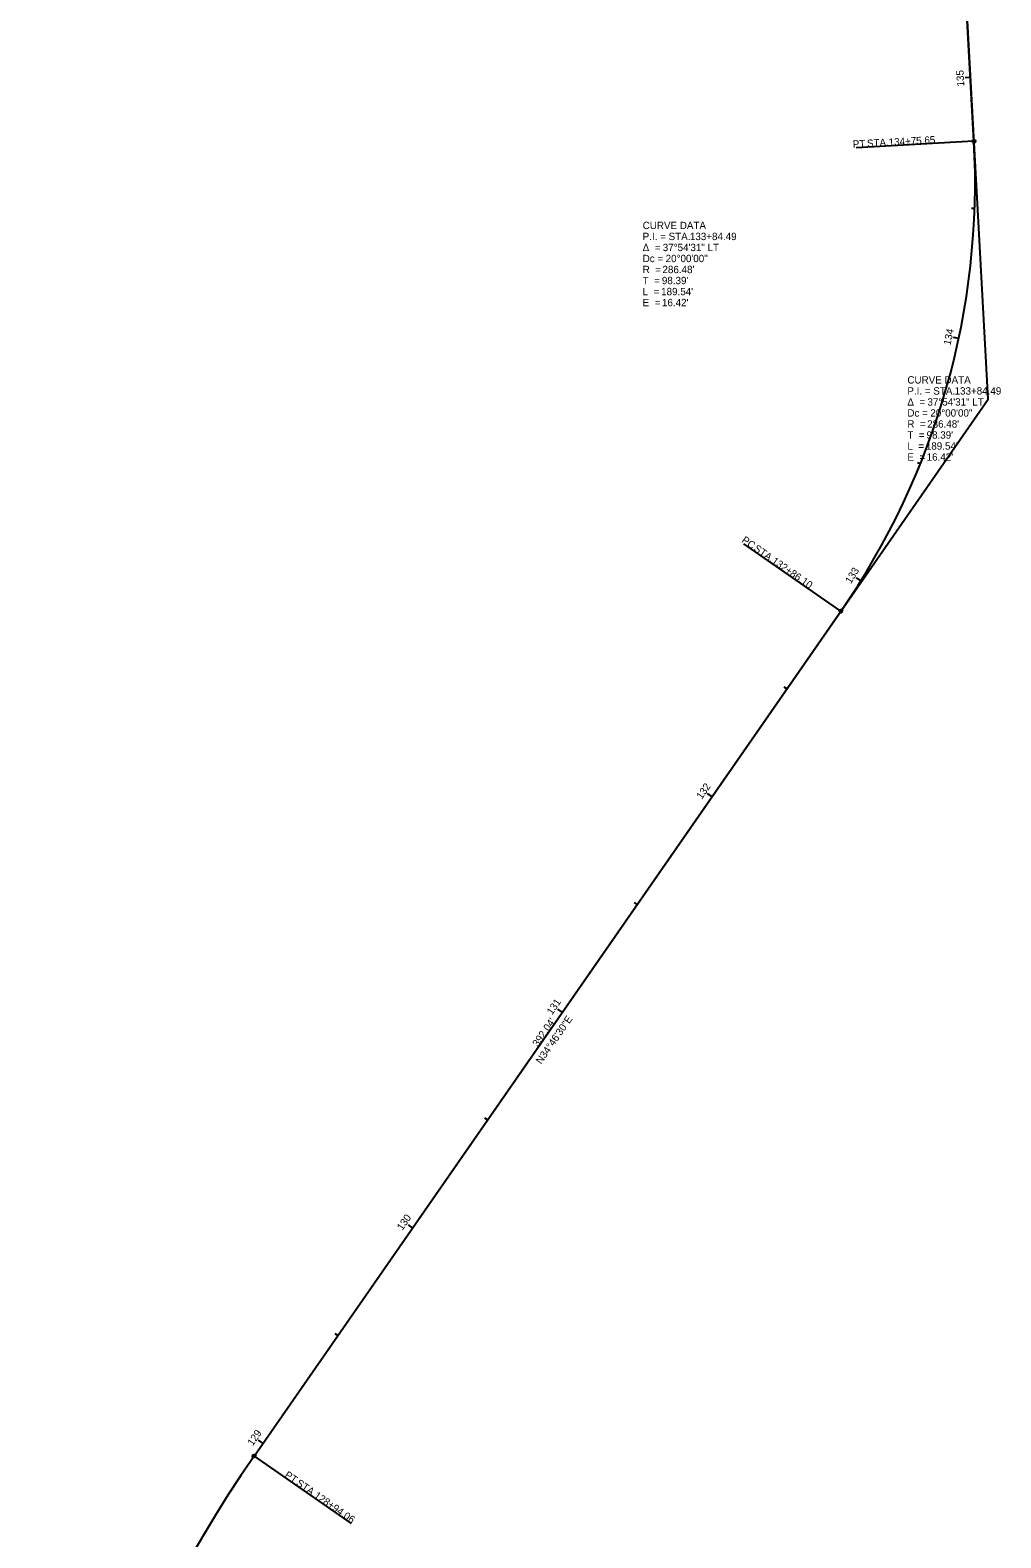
# Model space of a CAD drawing. Extents: x 177110 to 177558, y 286252 to 294117.
# Drawn here: x 177177 to 177547, y 288718 to 289293 of the extents above; entities that cross this region are included whole.
import ezdxf

# ---------------------------------------------------------------- set-up
doc = ezdxf.new("R2010")
doc.units = 0
for name, color, linetype in [('GE_X_Alignment_500_Bearings', 7, 'Continuous'), ('GE_X_Alignment_500_Cardinal_Points', 7, 'Continuous'), ('GE_X_Alignment_500_Curve_Data', 7, 'Continuous'), ('GE_X_Alignment_500_Distances', 7, 'Continuous'), ('GE_X_Alignment_500_Stations', 7, 'Continuous'), ('RW_X_CL', 7, 'Continuous'), ('RW_X_CL_100_Bearings', 7, 'Continuous'), ('RW_X_CL_100_Cardinal_Points', 7, 'Continuous'), ('RW_X_CL_100_Curve_Data', 7, 'Continuous'), ('RW_X_CL_100_Distances', 7, 'Continuous'), ('RW_X_CL_100_Stations', 7, 'Continuous'), ('SC_Scratch1', 7, 'Continuous')]:
    doc.layers.add(name, color=color, linetype=linetype)

msp = doc.modelspace()

# ---------------------------------------------------------------- linework, layer by layer
at = {"layer": 'GE_X_Alignment_500_Cardinal_Points'}
for p, q in [((177536.91, 289250.62), (177491.98, 289248.16)), ((177486.17, 289071.56), (177449.21, 289097.23)), ((177262.57, 288749.54), (177299.53, 288723.87))]:
    msp.add_line(p, q, dxfattribs=at)
for centre in [(177536.91, 289250.62), (177486.17, 289071.56), (177262.57, 288749.54)]:
    msp.add_circle(centre, 0.6, dxfattribs=at)
at = {"layer": 'GE_X_Alignment_500_Stations'}
for p, q in [((177535.58, 289274.93), (177533.58, 289274.82)), ((177531.08, 289175.41), (177529.91, 289175.66)), ((177493.82, 289083.16), (177492.8, 289083.8)), ((177437.06, 289000.84), (177436.08, 289001.52)), ((177380.03, 288918.7), (177379.04, 288919.38)), ((177322.99, 288836.56), (177321.35, 288837.7)), ((177265.96, 288754.42), (177264.97, 288755.1))]:
    msp.add_line(p, q, dxfattribs=at)
at = {"layer": 'RW_X_CL'}
for p, q in [((177536.91, 289250.62), (177528.82, 289398.35)), ((177262.57, 288749.54), (177486.17, 289071.56))]:
    msp.add_line(p, q, dxfattribs=at)
for centre, radius, start, end in [((177250.86, 289234.96), 286.48, 325.22501, 3.13348), ((177654.81, 288477.04), 477.61, 145.21153, 179.46165)]:
    msp.add_arc(centre, radius, start, end, dxfattribs=at)
at = {"layer": 'RW_X_CL_100_Cardinal_Points'}
for p, q in [((177536.91, 289250.62), (177491.98, 289248.16)), ((177486.17, 289071.56), (177449.21, 289097.23)), ((177262.57, 288749.54), (177299.53, 288723.87))]:
    msp.add_line(p, q, dxfattribs=at)
for centre in [(177536.91, 289250.62), (177486.17, 289071.56), (177262.57, 288749.54)]:
    msp.add_circle(centre, 0.6, dxfattribs=at)
at = {"layer": 'RW_X_CL_100_Stations'}
for p, q in [((177535.58, 289274.93), (177533.58, 289274.82)), ((177537.16, 289224.98), (177535.97, 289225.02)), ((177531.08, 289175.41), (177529.13, 289175.83)), ((177516.49, 289127.66), (177515.37, 289128.11)), ((177493.82, 289083.16), (177492.12, 289084.22)), ((177465.58, 289041.91), (177464.59, 289042.59)), ((177437.06, 289000.84), (177435.42, 289001.98)), ((177408.54, 288959.77), (177407.56, 288960.45)), ((177380.03, 288918.7), (177378.38, 288919.84)), ((177351.51, 288877.63), (177350.52, 288878.31)), ((177322.99, 288836.56), (177321.35, 288837.7)), ((177294.47, 288795.49), (177293.49, 288796.17)), ((177265.96, 288754.42), (177264.31, 288755.56))]:
    msp.add_line(p, q, dxfattribs=at)
at = {"layer": 'SC_Scratch1'}
for p, q in [((177542.29, 289152.38), (177527.16, 289428.73)), ((177262.57, 288749.54), (177542.29, 289152.38))]:
    msp.add_line(p, q, dxfattribs=at)
msp.add_arc((177250.86, 289234.96), 286.48, 325.22501, 3.13348, dxfattribs=at)

# ---------------------------------------------------------------- texts
at = {"layer": 'GE_X_Alignment_500_Bearings'}
msp.add_text('N34°46\'30"E', height=2.8, rotation=55.22501, dxfattribs=at).set_placement((177371.97, 288898.68))
at = {"layer": 'GE_X_Alignment_500_Cardinal_Points'}
for s, rotation, p in [('PT', 3.13348, (177490.82, 289248.13)), (' STA. ', 3.13348, (177495.17, 289248.37)), ('134+75.65', 3.13348, (177504.48, 289248.88)), ('PC', 325.22501, (177448.13, 289098.02)), (' STA. ', 325.22501, (177451.91, 289095.4)), ('132+86.10', 325.22501, (177459.57, 289090.08)), ('PT', 325.22501, (177273.93, 288741.7)), (' STA. ', 325.22501, (177277.5, 288739.22)), ('128+94.06', 325.22501, (177285.16, 288733.9))]:
    msp.add_text(s, height=2.8, rotation=rotation, dxfattribs=at).set_placement(p)
at = {"layer": 'GE_X_Alignment_500_Curve_Data'}
for s, p in [('CURVE DATA', (177511.54, 289158.29)), ('P.I. = STA. ', (177511.54, 289154.09)), ('133+84.49', (177529.53, 289154.09)), ('Δ  = ', (177511.54, 289149.89)), ('37°54\'31" LT', (177519.19, 289149.89)), ('Dc = ', (177511.54, 289145.69)), ('20°00\'00"', (177520.29, 289145.69)), ('T  = ', (177511.54, 289137.29)), ('R  = ', (177511.54, 289141.49)), ("98.39'", (177518.86, 289137.29)), ("286.48'", (177519.08, 289141.49)), ('L  = ', (177511.54, 289133.09)), ("189.54'", (177518.58, 289133.09)), ('E  = ', (177511.54, 289128.89)), ("16.42'", (177518.88, 289128.89))]:
    msp.add_text(s, height=2.8, dxfattribs=at).set_placement(p)
at = {"layer": 'GE_X_Alignment_500_Distances'}
msp.add_text("392.04'", height=2.8, rotation=55.22501, dxfattribs=at).set_placement((177370.67, 288905.28))
at = {"layer": 'GE_X_Alignment_500_Stations'}
for s, rotation, p in [('135', 93.13348, (177533.26, 289271.59)), ('130', 55.22501, (177319.07, 288835.3))]:
    msp.add_text(s, height=2.8, rotation=rotation, dxfattribs=at).set_placement(p)
at = {"layer": 'RW_X_CL_100_Bearings'}
msp.add_text('N34°46\'30"E', height=2.8, rotation=55.22501, dxfattribs=at).set_placement((177371.97, 288898.68))
at = {"layer": 'RW_X_CL_100_Cardinal_Points'}
for s, rotation, p in [('PT', 3.13348, (177490.82, 289248.13)), (' STA. ', 3.13348, (177495.17, 289248.37)), ('134+75.65', 3.13348, (177504.48, 289248.88)), ('PC', 325.22501, (177448.13, 289098.02)), (' STA. ', 325.22501, (177451.91, 289095.4)), ('132+86.10', 325.22501, (177459.57, 289090.08)), ('PT', 325.22501, (177273.93, 288741.7)), (' STA. ', 325.22501, (177277.5, 288739.22)), ('128+94.06', 325.22501, (177285.16, 288733.9))]:
    msp.add_text(s, height=2.8, rotation=rotation, dxfattribs=at).set_placement(p)
at = {"layer": 'RW_X_CL_100_Curve_Data'}
for s, p in [('CURVE DATA', (177410.66, 289217.16)), ('P.I. = STA. ', (177410.66, 289212.96)), ('133+84.49', (177428.65, 289212.96)), ('Δ  = ', (177410.66, 289208.76)), ('37°54\'31" LT', (177418.31, 289208.76)), ('Dc = ', (177410.66, 289204.56)), ('R  = ', (177410.66, 289200.36)), ("286.48'", (177418.2, 289200.36)), ('20°00\'00"', (177419.41, 289204.56)), ('T  = ', (177410.66, 289196.16)), ("98.39'", (177417.98, 289196.16)), ('L  = ', (177410.66, 289191.96)), ("189.54'", (177417.7, 289191.96)), ('E  = ', (177410.66, 289187.76)), ("16.42'", (177418.01, 289187.76))]:
    msp.add_text(s, height=2.8, dxfattribs=at).set_placement(p)
at = {"layer": 'RW_X_CL_100_Distances'}
msp.add_text("392.04'", height=2.8, rotation=55.22501, dxfattribs=at).set_placement((177370.67, 288905.28))
at = {"layer": 'RW_X_CL_100_Stations'}
for s, rotation, p in [('135', 93.13348, (177533.26, 289271.59)), ('134', 78.00413, (177527.96, 289172.73)), ('133', 58.00421, (177490, 289081.78)), ('132', 55.22501, (177433.18, 288999.62)), ('131', 55.22501, (177376.14, 288917.47)), ('130', 55.22501, (177319.07, 288835.3)), ('129', 55.22501, (177262.06, 288753.19))]:
    msp.add_text(s, height=2.8, rotation=rotation, dxfattribs=at).set_placement(p)

doc.saveas('drawing.dxf')
